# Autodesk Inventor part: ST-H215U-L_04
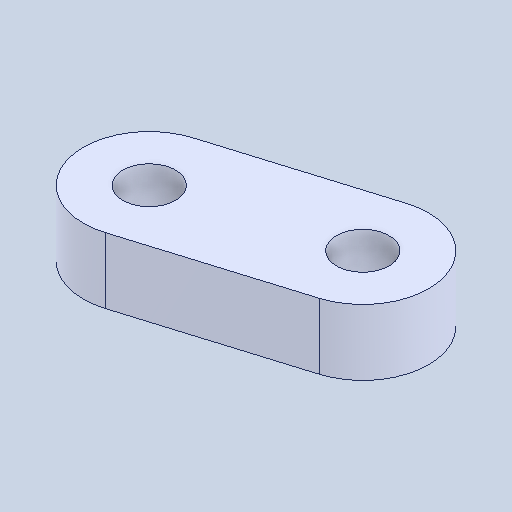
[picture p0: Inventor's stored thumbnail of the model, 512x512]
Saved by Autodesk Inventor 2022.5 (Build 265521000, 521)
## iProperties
Created: 2024-07
Part Number: ST-H215U-L_04
Material: 一般
Document SubType Name: Modeling
Designer: ImaoCorp
Density: 1 g/cm^3
Appearance: 既定
Author: ImaoCorp
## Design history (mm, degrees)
feature "ST-H215U-L_04"
node "ソリッド1"
